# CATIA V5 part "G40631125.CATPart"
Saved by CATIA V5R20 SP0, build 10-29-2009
Part number: G40631125
Revision: 3
Definition: design
Nomenclature: G40631125
Source: made
Description: NOT SPECIFIED
Bounding box of the stored display mesh (mm): x -62.5 to 62.5, y -12.5 to 12.5, z -31 to 0
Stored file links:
  C:\Users\Raffaele\Desktop\3D X SITO CF\BOLEX\30-GUIDE STRIP REF 406\G40631125.CATPart
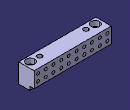
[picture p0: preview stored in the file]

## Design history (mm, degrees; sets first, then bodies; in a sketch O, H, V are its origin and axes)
Body1 "MANIFOLD_SOLID_BREP #3688" (main body)
  Solid1: solid without history
Body2 "MANIFOLD_SOLID_BREP #3826"
  Solid2: solid without history
Body3 "MANIFOLD_SOLID_BREP #3964"
  Solid3: solid without history
Body4 "MANIFOLD_SOLID_BREP #4102"
  Solid4: solid without history
Body5 "MANIFOLD_SOLID_BREP #4240"
  Solid5: solid without history
Body6 "MANIFOLD_SOLID_BREP #4378"
  Solid6: solid without history
Body7 "MANIFOLD_SOLID_BREP #4490"
  Solid7: solid without history
Body8 "MANIFOLD_SOLID_BREP #4602"
  Solid8: solid without history
Body9 "MANIFOLD_SOLID_BREP #4714"
  Solid9: solid without history
Body10 "MANIFOLD_SOLID_BREP #4826"
  Solid10: solid without history
Body11 "MANIFOLD_SOLID_BREP #4938"
  Solid11: solid without history
Body12 "MANIFOLD_SOLID_BREP #5050"
  Solid12: solid without history
Body13 "MANIFOLD_SOLID_BREP #5188"
  Solid13: solid without history
Body14 "MANIFOLD_SOLID_BREP #5326"
  Solid14: solid without history
Body15 "MANIFOLD_SOLID_BREP #5438"
  Solid15: solid without history
Body16 "MANIFOLD_SOLID_BREP #5550"
  Solid16: solid without history
Body17 "MANIFOLD_SOLID_BREP #5662"
  Solid17: solid without history
Body18 "MANIFOLD_SOLID_BREP #5774"
  Solid18: solid without history
Body19 "MANIFOLD_SOLID_BREP #5886"
  Solid19: solid without history
Body20 "MANIFOLD_SOLID_BREP #5998"
  Solid20: solid without history
Body21 "MANIFOLD_SOLID_BREP #6110"
  Solid21: solid without history
Body22 "MANIFOLD_SOLID_BREP #6222"
  Solid22: solid without history
Body23 "MANIFOLD_SOLID_BREP #6334"
  Solid23: solid without history
Body24 "MANIFOLD_SOLID_BREP #6446"
  Solid24: solid without history
Body25 "MANIFOLD_SOLID_BREP #6584"
  Solid25: solid without history
Body26 "MANIFOLD_SOLID_BREP #6722"
  Solid26: solid without history
Body27 "MANIFOLD_SOLID_BREP #6834"
  Solid27: solid without history
Body28 "MANIFOLD_SOLID_BREP #6946"
  Solid28: solid without history
Body29 "MANIFOLD_SOLID_BREP #7058"
  Solid29: solid without history
Body30 "MANIFOLD_SOLID_BREP #7170"
  Solid30: solid without history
